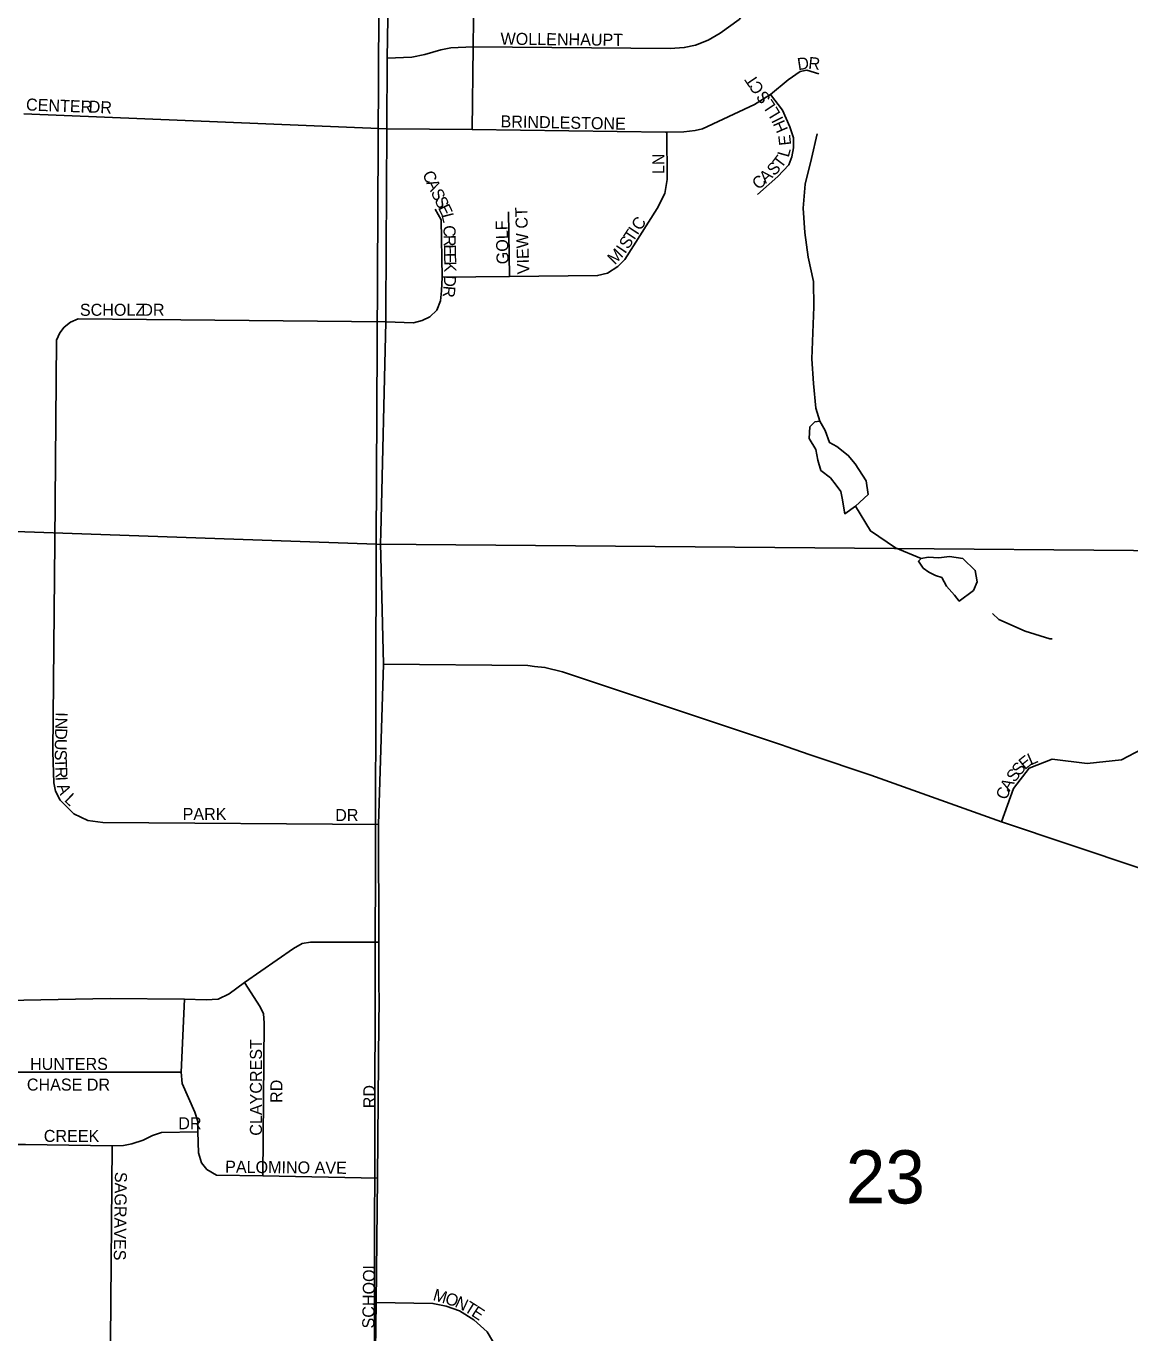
# Model space of a CAD drawing. Extents: x 8.5 to 81.5, y -1.2 to 22.4.
# Drawn here: x 52.954 to 53.822, y 18.242 to 19.27 of the extents above; entities that cross this region are included whole.
import ezdxf

# ---------------------------------------------------------------- set-up
doc = ezdxf.new("R2010")
doc.units = 0
for name, color, linetype in [('GM_X_City_Street', 7, 'Continuous'), ('GM_X_City_Street_Text', 7, 'Continuous'), ('GM_X_Minor_Lake', 7, 'Continuous'), ('GM_X_Minor_River', 7, 'Continuous'), ('GM_X_Section', 7, 'Continuous'), ('GM_X_Section_Text', 7, 'Continuous'), ('GM_X_US_Route', 7, 'Continuous')]:
    doc.layers.add(name, color=color, linetype=linetype)

msp = doc.modelspace()

# ---------------------------------------------------------------- linework, layer by layer
at = {"layer": 'GM_X_City_Street'}
for points in [[(53.2381, 19.2451), (53.2383, 19.245), (53.2575, 19.2457), (53.2678, 19.2478), (53.2803, 19.2517), (53.2883, 19.2532), (53.3057, 19.2539), (53.4608, 19.2526), (53.4718, 19.2534), (53.4807, 19.2553), (53.4906, 19.2591), (53.5, 19.2646), (53.5151, 19.2755), (53.5287, 19.293), (53.5334, 19.3026), (53.537, 19.3129), (53.5394, 19.3216), (53.5395, 19.4061), (53.5394, 19.439), (53.539, 19.4451), (53.5361, 19.4503), (53.5308, 19.4566), (53.5232, 19.4612)], [(53.305, 19.189), (53.3057, 19.2539), (53.3073, 19.3832), (53.3095, 19.3938), (53.314, 19.4011), (53.3224, 19.405)], [(53.238, 19.1895), (53.305, 19.189), (53.4572, 19.1867), (53.4581, 19.1867), (53.4716, 19.1871), (53.4804, 19.1881), (53.4862, 19.1895), (53.5272, 19.2086), (53.5385, 19.2156), (53.5397, 19.2165), (53.5537, 19.228), (53.563, 19.2345), (53.5683, 19.2356), (53.5778, 19.2326)], [(53.5295, 19.1377), (53.5454, 19.1519), (53.554, 19.1611), (53.5564, 19.1673), (53.5578, 19.1746), (53.5578, 19.1824), (53.5548, 19.191), (53.5491, 19.2042), (53.5397, 19.2165)], [(52.9524, 19.2013), (53.238, 19.1895)], [(53.2814, 19.0728), (53.3344, 19.0732), (53.4037, 19.074), (53.4116, 19.0759), (53.4195, 19.0811), (53.4251, 19.0866), (53.4505, 19.1267), (53.4567, 19.1385), (53.4583, 19.1496), (53.4581, 19.1867)], [(53.2372, 19.0376), (53.259, 19.0368), (53.2656, 19.0385), (53.2718, 19.0416), (53.2772, 19.0467), (53.28, 19.0541), (53.2809, 19.062), (53.2814, 19.0728), (53.2806, 19.1179), (53.276, 19.1261)], [(53.3344, 19.0732), (53.3335, 19.1242)], [(53.2313, 18.642), (53.0146, 18.6436), (53.0028, 18.6452), (52.9918, 18.6505), (52.981, 18.6611), (52.9772, 18.6682), (52.9759, 18.6748), (52.9751, 18.6992), (52.9767, 18.8646), (52.978, 19.0231), (52.9807, 19.0289), (52.9842, 19.0333), (52.9891, 19.0373), (52.9951, 19.0398)], [(52.9951, 19.0398), (53.2372, 19.0376)], [(53.2317, 18.5184), (53.2316, 18.5496), (53.2313, 18.642), (53.2352, 18.7682)], [(53.7215, 18.6441), (53.7307, 18.6703), (53.7432, 18.6864), (53.7611, 18.6936), (53.7887, 18.69), (53.8157, 18.6929), (53.8318, 18.7013)], [(52.8656, 18.427), (52.8665, 18.4479), (52.8686, 18.4769), (52.8697, 18.4878), (52.8721, 18.4926), (52.8777, 18.4992), (52.8865, 18.5021), (52.8975, 18.5028), (53.0204, 18.5053), (53.0789, 18.5046), (53.0959, 18.504), (53.1052, 18.5047), (53.1139, 18.5089), (53.126, 18.5178), (53.1646, 18.5444), (53.1712, 18.5485), (53.1779, 18.5495), (53.2316, 18.5496)], [(53.1403, 18.3656), (53.1415, 18.4859), (53.141, 18.4931), (53.1383, 18.4986), (53.126, 18.5178)], [(53.2282, 18.0942), (53.2283, 18.0954), (53.2283, 18.1014), (53.228, 18.1533), (53.2295, 18.2661), (53.2306, 18.3639), (53.2316, 18.4872), (53.2318, 18.5015), (53.2317, 18.5184)], [(53.0789, 18.5046), (53.0761, 18.4473), (53.077, 18.4383), (53.087, 18.4158), (53.0892, 18.4083), (53.0893, 18.4003), (53.0898, 18.3838), (53.0922, 18.376), (53.0964, 18.3705), (53.104, 18.3663), (53.1403, 18.3656), (53.2306, 18.3639)], [(52.8665, 18.4479), (52.9246, 18.4471), (53.0761, 18.4473)], [(52.9246, 18.4471), (52.9244, 18.4127), (52.9254, 18.4027), (52.9275, 18.398), (52.9309, 18.3942), (52.9368, 18.3921), (52.9425, 18.3904), (52.9537, 18.3903), (53.022, 18.3893), (53.0309, 18.3896), (53.0373, 18.3907), (53.0463, 18.3938), (53.0537, 18.3975), (53.0607, 18.3997), (53.0893, 18.4003)], [(52.9851, 18.0432), (53.0048, 18.0412), (53.0121, 18.0438), (53.018, 18.053), (53.03, 18.1682), (53.0297, 18.1818), (53.0281, 18.194), (53.0254, 18.2069), (53.0232, 18.2187), (53.0214, 18.2297), (53.0206, 18.2362), (53.022, 18.3893)], [(53.3324, 18.2079), (53.3253, 18.2288), (53.3169, 18.243), (53.3063, 18.2523), (53.295, 18.2594), (53.2847, 18.263), (53.2741, 18.2653), (53.2295, 18.2661)]]:
    msp.add_lwpolyline(points, dxfattribs=at)
at = {"layer": 'GM_X_Minor_Lake'}
for points in [[(53.6066, 18.8925), (53.6166, 18.9018), (53.6149, 18.9125), (53.6063, 18.9259), (53.6008, 18.9324), (53.5918, 18.9394), (53.5861, 18.9425), (53.5828, 18.9521), (53.5784, 18.9594), (53.5746, 18.959), (53.5707, 18.9549), (53.5702, 18.9458), (53.5754, 18.937), (53.5768, 18.9287), (53.5793, 18.9206), (53.5868, 18.9148)], [(53.5868, 18.9148), (53.5913, 18.9091), (53.595, 18.9041), (53.596, 18.8987), (53.5981, 18.8866), (53.6066, 18.8925)], [(53.6993, 18.8261), (53.7021, 18.8329), (53.7007, 18.842), (53.691, 18.8513), (53.6804, 18.853), (53.672, 18.852), (53.6637, 18.8525), (53.6583, 18.8514), (53.656, 18.8492), (53.6597, 18.8438), (53.6642, 18.8407), (53.6695, 18.838), (53.6744, 18.8364)], [(53.6744, 18.8364), (53.6781, 18.8295), (53.6844, 18.8226), (53.6882, 18.8179), (53.6993, 18.8261)]]:
    msp.add_lwpolyline(points, dxfattribs=at)
at = {"layer": 'GM_X_Minor_River'}
for points in [[(53.5765, 19.1854), (53.5719, 19.166), (53.567, 19.1459), (53.5654, 19.1269), (53.5666, 19.1079), (53.5693, 19.0885), (53.5734, 19.0692), (53.5738, 19.0494), (53.5723, 19.0084), (53.5735, 18.989), (53.5754, 18.9696), (53.5784, 18.9594)], [(53.6066, 18.8925), (53.6184, 18.8731), (53.6381, 18.8598), (53.6583, 18.8514)], [(53.7143, 18.8082), (53.7194, 18.8034), (53.7399, 18.7943), (53.7593, 18.7882), (53.7612, 18.7882)]]:
    msp.add_lwpolyline(points, dxfattribs=at)
at = {"layer": 'GM_X_Section'}
for points in [[(52.284, 19.8673), (53.2345, 19.8635), (53.2294, 18.8627), (52.2136, 18.8983), (52.2219, 19.2023)], [(53.2345, 19.8635), (53.2697, 19.8629), (54.1332, 19.86), (54.1387, 19.8542), (54.1465, 19.845), (54.1513, 19.8385), (54.1598, 19.8273), (54.1654, 19.8204), (54.1691, 19.8165), (54.1807, 19.8076), (54.1866, 19.8022), (54.2077, 19.7764), (54.2144, 19.7672), (54.2299, 19.7453), (54.2329, 18.8542), (53.2294, 18.8627)], [(52.2136, 18.8983), (53.2294, 18.8627), (53.2272, 17.8352), (52.2149, 17.8371)]]:
    msp.add_lwpolyline(points, close=True, dxfattribs=at)
msp.add_lwpolyline([(53.2272, 17.8352), (53.2294, 18.8627), (54.2329, 18.8542)], dxfattribs=at)
at = {"layer": 'GM_X_US_Route'}
for points in [[(53.2402, 19.376), (53.2402, 19.3698), (53.2381, 19.2451), (53.238, 19.1895), (53.2372, 19.0463)], [(53.2372, 19.0463), (53.2372, 19.0376), (53.2332, 18.8712)], [(53.2332, 18.8712), (53.233, 18.8635), (53.2352, 18.7682), (53.3488, 18.7671), (53.3541, 18.7665)], [(53.3541, 18.7665), (53.3622, 18.7656), (53.376, 18.7622), (53.5491, 18.7044), (53.5521, 18.7034)], [(53.5521, 18.7034), (53.5708, 18.697)], [(53.5708, 18.697), (53.6186, 18.6809), (53.7215, 18.6441), (53.8301, 18.6076), (53.833, 18.6066)]]:
    msp.add_lwpolyline(points, dxfattribs=at)

# ---------------------------------------------------------------- texts
at = {"layer": 'GM_X_City_Street_Text'}
for s, rotation, p in [('WOLLENHAUPT', 359.4546, (53.3273, 19.2556)), ('D', 8.6431, (53.5615, 19.2355)), ('R', 353.8207, (53.5691, 19.2367)), ('T', 124.372, (53.531, 19.2269)), ('C', 124.3772, (53.5352, 19.2207)), ('S', 124.3933, (53.5404, 19.2132)), ('CENTER', 357.8801, (52.954, 19.2039)), ('DR', 356.989, (53.0032, 19.2023)), ('L', 123.8097, (53.5442, 19.2075)), ('L', 121.156, (53.5479, 19.2014)), ('BRINDLESTONE', 358.9094, (53.3273, 19.1906)), ('I', 116.9794, (53.5501, 19.1971)), ('H', 113.5692, (53.5537, 19.1889)), ('E', 96.2212, (53.556, 19.1768)), ('LN', 90, (53.4563, 19.1538)), ('T', 52.895, (53.5482, 19.1577)), ('L', 74.3867, (53.5539, 19.1665)), ('C', 295.3162, (53.2656, 19.1538)), ('A', 41.737, (53.5359, 19.146)), ('S', 44.8876, (53.5425, 19.1519)), ('A', 295.314, (53.2688, 19.147)), ('C', 41.7525, (53.5303, 19.141)), ('S', 295.2942, (53.2723, 19.1395)), ('S', 295.3186, (53.2752, 19.1334)), ('E', 295.3189, (53.278, 19.1274)), ('L', 284.3543, (53.2807, 19.1218)), ('VIEW CT', 92.0122, (53.3501, 19.0752)), ('C', 271.4813, (53.2824, 19.1134)), ('GOLF', 91.5903, (53.3338, 19.083)), ('C', 56.6984, (53.4374, 19.1087)), ('R', 271.02, (53.2826, 19.1059)), ('S', 56.5925, (53.4277, 19.0941)), ('T', 56.7, (53.4314, 19.0997)), ('I', 56.6737, (53.4351, 19.1053)), ('E', 271.0247, (53.2828, 19.0984)), ('M', 45.1288, (53.4171, 19.082)), ('I', 56.2103, (53.4254, 19.0906)), ('E', 271.0108, (53.2829, 19.0918)), ('K', 271.0296, (53.283, 19.0851)), ('D', 266.6541, (53.2831, 19.0745)), ('R', 264.7726, (53.2826, 19.0662)), ('SCHOLZ', 0, (52.9965, 19.0423)), ('DR', 0, (53.0448, 19.0423)), ('N', 268.5403, (52.9773, 18.7263)), ('I', 268.5133, (52.9774, 18.7305)), ('D', 268.5357, (52.9771, 18.718)), ('U', 268.6528, (52.9769, 18.7096)), ('S', 270.6234, (52.9767, 18.7009)), ('T', 272.0522, (52.9767, 18.694)), ('E', 38.5147, (53.7396, 18.6847)), ('L', 23.4964, (53.7443, 18.6885)), ('R', 272.3924, (52.977, 18.6873)), ('S', 51.9333, (53.7317, 18.6747)), ('S', 51.0373, (53.7358, 18.6799)), ('I', 273.5228, (52.9773, 18.6796)), ('A', 290.6302, (52.9782, 18.6724)), ('C', 70.9506, (53.7256, 18.661)), ('A', 60.697, (53.7278, 18.6677)), ('L', 316.2359, (52.9837, 18.6608)), ('PARK', 0, (53.0773, 18.6456)), ('DR', 0, (53.1973, 18.6448)), ('CLAYCREST', 90, (53.1397, 18.3972)), ('HUNTERS', 0, (52.9573, 18.449)), ('CHASE DR', 0, (52.9548, 18.4327)), ('RD', 90, (53.1558, 18.423)), ('RD', 90, (53.2288, 18.4188)), ('DR', 0, (53.0739, 18.4023)), ('CREEK', 0, (52.9681, 18.3923)), ('PALOMINO AVE', 359.4539, (53.1107, 18.3681)), ('SAGRAVES', 269.2126, (53.0241, 18.3688)), ('SCHOOL', 89.1308, (53.228, 18.2455)), ('M', 343.852, (53.2736, 18.268)), ('O', 342.277, (53.2831, 18.2653)), ('N', 334.921, (53.2908, 18.2629)), ('T', 328.2958, (53.2981, 18.2595)), ('E', 326.9693, (53.3037, 18.256))]:
    msp.add_text(s, height=0.00947, rotation=rotation, dxfattribs=at).set_placement(p)
at = {"layer": 'GM_X_Section_Text'}
msp.add_text('23', height=0.04186, rotation=0, dxfattribs=at).set_placement((53.5989, 18.3439))

doc.saveas('drawing.dxf')
